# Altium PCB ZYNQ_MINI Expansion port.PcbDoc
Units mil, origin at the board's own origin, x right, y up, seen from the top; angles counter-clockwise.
Board outline 3075.9 x 3587.68 mil, 12 copper layers (Top Layer 1, Mid-Layer 2, Mid-Layer 3, Mid-Layer 4, Mid-Layer 5, Mid-Layer 6, Mid-Layer 7, Mid-Layer 8, Mid-Layer 9, Mid-Layer 10, Mid-Layer 11, Bottom Layer 12), stack 61.812 mil thick; 3 components, 0 nets, 80 pads, 24 vias.
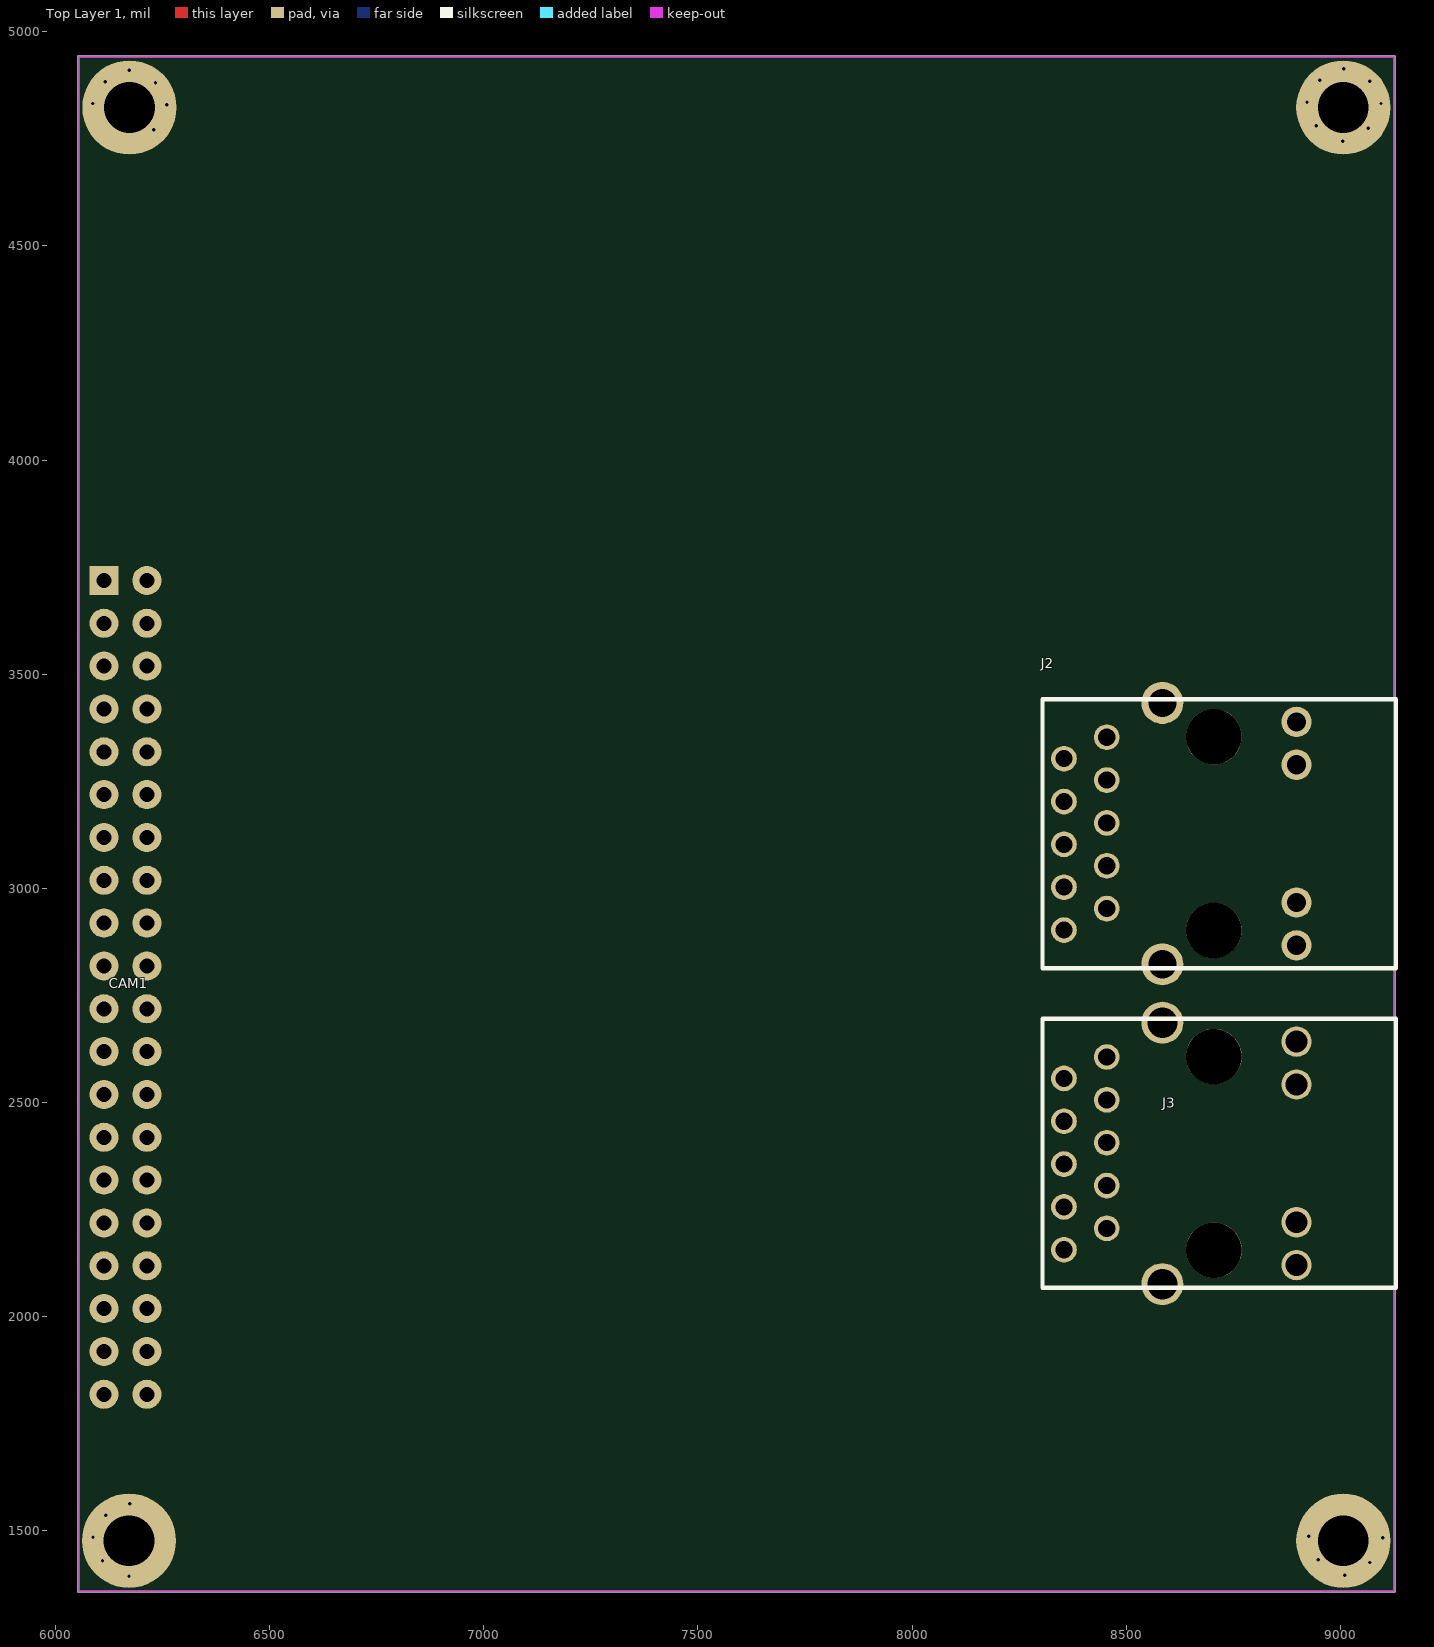
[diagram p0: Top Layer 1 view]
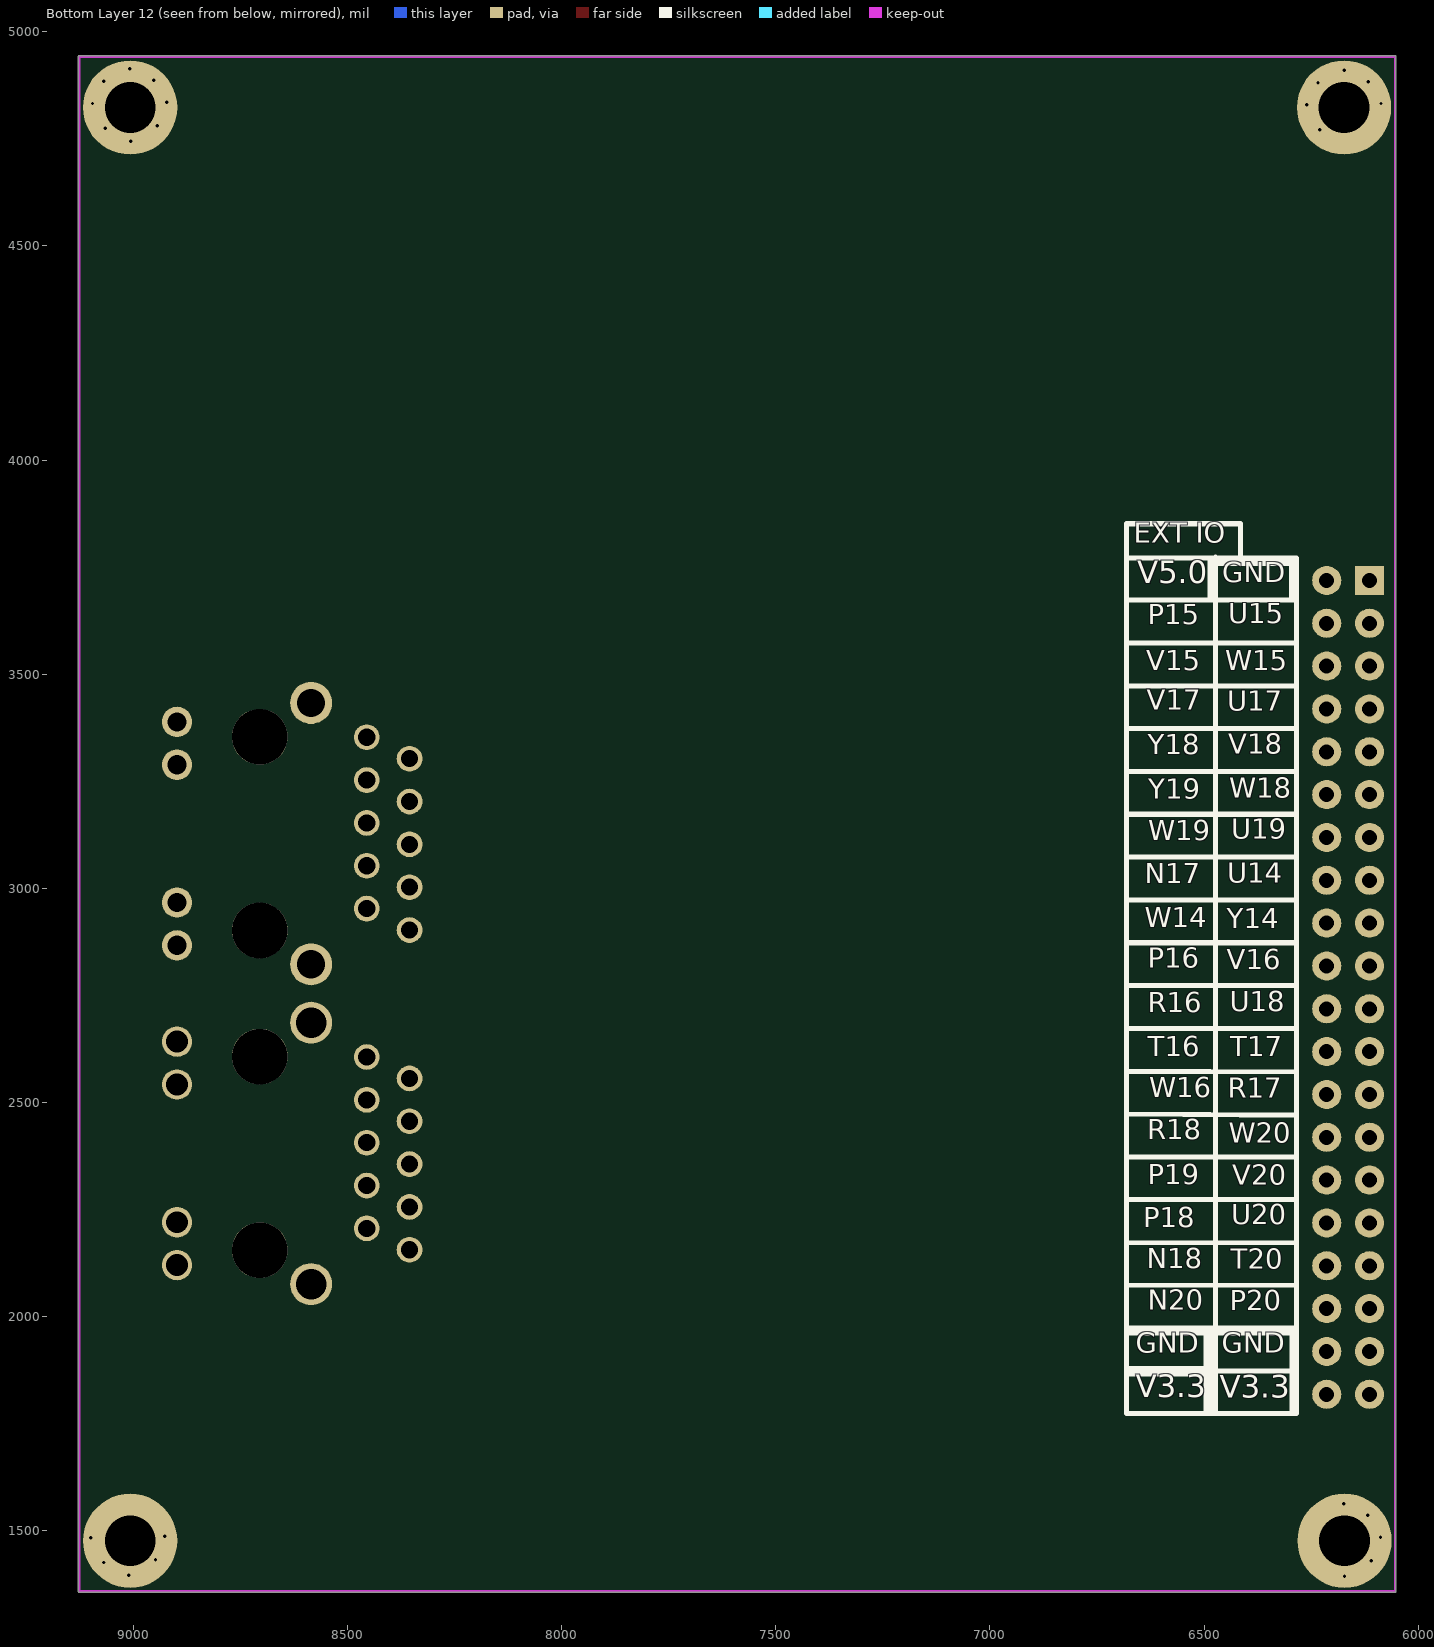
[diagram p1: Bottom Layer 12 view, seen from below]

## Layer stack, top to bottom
Top Solder: solder mask 0.4, Solder Resist, Dk 3.5
Top Layer 1: signal copper 1.378
Dielectric 1: core 2.9528, FR-4, Dk 4.2
Mid-Layer 2: signal copper 0.689
Dielectric 2: prepreg 4.5276, FR-4, Dk 4.2
Mid-Layer 3: signal copper 0.689
Dielectric 3: core 5.9055, FR-4, Dk 4.2
Mid-Layer 4: signal copper 0.689
Dielectric 4: prepreg 4.5276, FR-4, Dk 4.2
Mid-Layer 5: signal copper 0.689
Dielectric 5: core 5.9055, Dk 4.2
Mid-Layer 6: signal copper 0.689
Dielectric 6: prepreg 4.5276, Dk 4.2
Mid-Layer 7: signal copper 0.689
Dielectric 7: core 5.9055, Dk 4.2
Mid-Layer 8: signal copper 0.689
Dielectric 8: prepreg 4.5276, Dk 4.2
Mid-Layer 9: signal copper 0.689
Dielectric 9: core 5.9055, Dk 4.2
Mid-Layer 10: signal copper 0.689
Dielectric 10: prepreg 4.5276, Dk 4.2
Mid-Layer 11: signal copper 0.689
Dielectric 11: core 2.9528, FR-4, Dk 4.2
Bottom Layer 12: signal copper 1.378
Bottom Solder: solder mask 0.4, Solder Resist, Dk 3.5

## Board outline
6052.06,2142.67 cw(c6054.57,2142.69) 6052.06,2142.69 6052.06,4941.65 cw(c6054.57,4941.65) 6054.57,4944.17 7925.88,4944.17 cw(c7925.88,4941.65) 7925.91,4944.17 9125.44,4944.17 cw(c9125.44,4941.65) 9127.96,4941.65 9127.96,1359 cw(c9125.44,1359) 9125.44,1356.48 6054.57,1356.48 cw(c6054.57,1359) 6052.06,1359

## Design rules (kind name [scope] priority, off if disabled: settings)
AssemblyTestPointUsage [All] p1 off:
AssemblyTestpoint [All] p1 off: testpointundercomponent=TRUE minsize=40 maxsize=100 preferedsize=60 minholesize=0 maxholesize=40 preferedholesize=32 testpointgrid=1 usegrid=TRUE gridtolerance=0.01 allowsidetop=TRUE allowsidebottom=TRUE
Clearance Clearance_2 [IsTrack vs isvia] p1: gap=5.5 ignorepadtopadclearanceinfootprint=FALSE
Clearance [All] p2: gap=4 ignorepadtopadclearanceinfootprint=FALSE
ComponentClearance [All] p1 off: gap=10 collisioncheckmode=3 verticalgap=10 showdistances=FALSE
DiffPairsRouting [All] p1 off: maxlimit=10 minlimit=10 mostfreqgap=10 toplayer_minwidth=15 toplayer_maxwidth=15 toplayer_prefwidth=15 midlayer1_minwidth=15 midlayer1_maxwidth=15 midlayer1_prefwidth=15 midlayer2_minwidth=15 midlayer2_maxwidth=15 midlayer2_prefwidth=15 midlayer3_minwidth=15 midlayer3_maxwidth=15 midlayer3_prefwidth=15 midlayer4_minwidth=15 midlayer4_maxwidth=15 midlayer4_prefwidth=15 midlayer5_minwidth=15 midlayer5_maxwidth=15 midlayer5_prefwidth=15 midlayer6_minwidth=15 midlayer6_maxwidth=15 midlayer6_prefwidth=15 midlayer7_minwidth=15 midlayer7_maxwidth=15 midlayer7_prefwidth=15 midlayer8_minwidth=15 midlayer8_maxwidth=15 midlayer8_prefwidth=15 midlayer9_minwidth=15 midlayer9_maxwidth=15 midlayer9_prefwidth=15 midlayer10_minwidth=15 midlayer10_maxwidth=15 midlayer10_prefwidth=15 bottomlayer_minwidth=15 bottomlayer_maxwidth=15 bottomlayer_prefwidth=15 maxuncoupledlength=500
FabricationTestPointUsage [All] p1 off: valid=0 allowmultiple=FALSE
FabricationTestpoint [All] p1 off: side=3 testpointundercomponent=TRUE minsize=40 maxsize=100 preferedsize=60 minholesize=0 maxholesize=40 preferedholesize=32 testpointgrid=1 allowsidetop=TRUE allowsidebottom=TRUE usegrid=TRUE gridtolerance=0.01
FanoutControl Fanout_BGA [IsBGA] p1 off: bgadir=Out bgaviamode=Centered fanoutstyle=Auto fanoutdirection=Alternating viagrid=1 // Fanout_BGA (Default Rule)
FanoutControl Fanout_LCC [IsLCC] p2 off: bgadir=Out bgaviamode=Centered fanoutstyle=Auto fanoutdirection=Alternating viagrid=1 // Fanout_LCC (Default Rule)
FanoutControl Fanout_SOIC [IsSOIC] p3 off: bgadir=Out bgaviamode=Centered fanoutstyle=Auto fanoutdirection=Alternating viagrid=1 // Fanout_SOIC (Default Rule)
FanoutControl Fanout_Small [(CompPinCount < 5)] p4 off: bgadir=Out bgaviamode=Centered fanoutstyle=Auto fanoutdirection=OutThenIn viagrid=1 // Fanout_Small (Default Rule)
FanoutControl Fanout_Default [All] p5 off: bgadir=Out bgaviamode=Centered fanoutstyle=Auto fanoutdirection=Alternating viagrid=1 // Fanout_Default (Default Rule)
Height [All] p1 off: minheight=0 maxheight=1000 prefheight=500
HoleSize [All] p1 off: absolutevalues=TRUE maxlimit=100 minlimit=1 maxpercent=80.000 minpercent=20.000
HoleToHoleClearance [All] p1 off: gap=10 allowstackedmicrovias=TRUE
LayerPairs [All] p1 off: enforce=TRUE
MinimumSolderMaskSliver [All] p1 off: minsoldermaskwidth=10
NetAntennae [All] p1 off: netantennaetolerance=0
PasteMaskExpansion [All] p1 off: expansion=0
PlaneConnect [All] p1: planeconnectstyle=Direct reliefexpansion=20 reliefentries=4 reliefconductorwidth=10 reliefairgap=10
PolygonConnect [All] p1: connectstyle=Direct reliefconductorwidth=10 reliefentries=4 polygonreliefangle="90 Angle" airgapwidth=10
RoutingCorners [All] p1 off: cornerstyle=45-Degree minsetback=100 maxsetback=100
RoutingLayers [All] p1 off: top layer_v5=TRUE mid layer 1_v5=TRUE mid layer 2_v5=TRUE mid layer 3_v5=TRUE mid layer 4_v5=TRUE mid layer 5_v5=TRUE mid layer 6_v5=TRUE mid layer 7_v5=TRUE mid layer 8_v5=TRUE mid layer 9_v5=TRUE mid layer 10_v5=TRUE bottom layer_v5=TRUE
RoutingPriority [All] p1 off: routingpriority=0
RoutingTopology [All] p1 off: topology=Shortest
RoutingVias [All] p1: holewidth=7.87 width=15.75 viastyle="Through Hole" minholewidth=7.87 minwidth=15.75 maxholewidth=129.92 maxwidth=196.85
SilkToSilkClearance [All] p1 off: silktosilkclearance=10
SilkToSolderMaskClearance [IsPad] p1 off: minsilkscreentomaskgap=10 clearancetoexposedcopper=TRUE
SolderMaskExpansion [All] p1 off: expansion=4
UnpouredPolygon [All] p1 off:
Width [All] p1: maxlimit=20 minlimit=3.5 preferedwidth=3.9 toplayer_prefwidth=4.5 midlayer1_maxwidth=8 midlayer2_maxwidth=8 midlayer3_maxwidth=8 midlayer4_maxwidth=8 midlayer5_maxwidth=8 midlayer6_maxwidth=8 midlayer7_maxwidth=8 midlayer8_maxwidth=8 midlayer9_maxwidth=8 midlayer10_maxwidth=8 bottomlayer_prefwidth=4.5 minimp=50.000000 maximp=50.000000 favimp=50.000000
4 further rules are at their usual default settings.

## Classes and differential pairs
component class 09ZYNQ_IO: CAM1
component class 07ZYNQ_ETH_PHY: C144
component class 12_OLED: C? J?

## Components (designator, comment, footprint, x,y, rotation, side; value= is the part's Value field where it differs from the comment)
CAM1 "40针双排" 40针双排 6117.63,2721.92 r0 top locked
J2 "HR911130A" HR911130A#1 8701.62,3129.53 r0 top locked
J3 "HR911130A" HR911130A#2 8701.63,2383.07 r0 top locked

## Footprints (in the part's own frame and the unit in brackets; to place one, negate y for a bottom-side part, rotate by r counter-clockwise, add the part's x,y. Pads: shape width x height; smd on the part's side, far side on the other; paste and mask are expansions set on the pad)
40针双排 [mil]
  rect 68x68 hole 35: 1(-4,997)
  round 68 hole 35: 2(-4,897) 3(-4,797) 4(-4,697) 5(-4,597) 6(-4,497) 7(-4,397) 8(-4,297) 9(-4,197) 10(-4,97) 11(-4,-3) 12(-4,-103) 13(-4,-203) 14(-4,-303) 15(-4,-403) 16(-4,-503) 17(-4,-603) 18(-4,-703) 19(-4,-803) 20(-4,-903) 21(96,-903) 22(96,-803) 23(96,-703) 24(96,-603) 25(96,-503) 26(96,-403) 27(96,-303) 28(96,-203) 29(96,-103) 30(96,-3) 31(96,97) 32(96,197) 33(96,297) 34(96,397) 35(96,497) 36(96,597) 37(96,697) 38(96,797) 39(96,897) 40(96,997)
HR911130A#1 [mil]
  round 70.87 hole 45: 11(196,-262.54) 12(196,-162.54) 13(196,159.12) 14(196,259.12)
  round 98 hole 66: 15(-116.99,-306.83) 16(-116.99,303.41)
  round 129.92 hole 129.92: 17(3.08,-227.69) 18(3.08,224.27)
  round 60 hole 40: P1(-346.92,-226.71) P2(-246.92,-176.71) P3(-346.92,-126.71) P4(-246.92,-76.71) P5(-346.92,-26.71) P6(-246.92,23.29) P7(-346.92,73.29) P8(-246.92,123.29) P9(-346.92,173.29) P10(-246.92,223.29)
  silkscreen extent -397,-316 428,312
HR911130A#2 [mil]
  round 70.87 hole 51.18: 11(196,-262.54) 12(196,-162.54) 13(196,159.12) 14(196,259.12)
  round 98 hole 70.87: 15(-116.99,-306.83) 16(-116.99,303.41)
  round 129.92 hole 129.92: 17(3.08,-227.69) 18(3.08,224.27)
  round 60 hole 40: P1(-346.92,-226.71) P2(-246.92,-176.71) P3(-346.92,-126.71) P4(-246.92,-76.71) P5(-346.92,-26.71) P6(-246.92,23.29) P7(-346.92,73.29) P8(-246.92,123.29) P9(-346.92,173.29) P10(-246.92,223.29)
  silkscreen extent -397,-316 428,312

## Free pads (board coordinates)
  round 220 hole 118.5: 2(6172,1477) 2(6173,4823) 2(9007,1477) 2(9007,4823)

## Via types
v1: diameter 15.75, hole 7.87, Top Layer 1 to Bottom Layer 12, tented both sides, 24 vias

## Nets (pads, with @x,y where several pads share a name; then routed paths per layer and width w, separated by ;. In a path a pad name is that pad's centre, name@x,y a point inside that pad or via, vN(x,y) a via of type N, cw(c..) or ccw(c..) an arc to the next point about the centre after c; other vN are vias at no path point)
pads on no net: CAM1.1 CAM1.2 CAM1.3 CAM1.4 CAM1.5 CAM1.6 CAM1.7 CAM1.8 CAM1.9 CAM1.10 CAM1.11 CAM1.12 CAM1.13 CAM1.14 CAM1.15 CAM1.16 CAM1.17 CAM1.18 CAM1.19 CAM1.20 CAM1.21 CAM1.22 CAM1.23 CAM1.24 CAM1.25 CAM1.26 CAM1.27 CAM1.28 CAM1.29 CAM1.30 CAM1.31 CAM1.32 CAM1.33 CAM1.34 CAM1.35 CAM1.36 CAM1.37 CAM1.38 CAM1.39 CAM1.40 J2.11 J2.12 J2.13 J2.14 J2.15 J2.16 J2.17 J2.18 J2.P1 J2.P2 J2.P3 J2.P4 J2.P5 J2.P6 J2.P7 J2.P8 J2.P9 J2.P10 J3.11 J3.12 J3.13 J3.14 J3.15 J3.16 J3.17 J3.18 J3.P1 J3.P2 J3.P3 J3.P4 J3.P5 J3.P6 J3.P7 J3.P8 J3.P9 J3.P10
copper on no net:
  other v1: 6172,1394.25 9010,1396.25 9069,1426.25 6110,1430.25 8948,1432.25 9099,1484.25 6088,1485.25 8926,1487.25 6118,1536.25 6174,1563.25 9006,4744.25 6230,4771.25 9065,4774.25 8944,4780.25 6260,4829.25 6087,4832.25 9095,4832.25 8922,4835.25 6234,4881.25 6117,4883.25 9069,4884.25 8952,4886.25 6173,4910.25 9008,4913.25

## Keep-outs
Keep-Out Layer:
  lines w5: 6054.57,2142.69 6054.57,4941.65 7925.88,4941.65 ; 6054.57,2142.79 6054.57,1359 9125.44,1359 9125.44,4941.65 7801.69,4941.65 ; 7703.73,4941.39 8162.1,4941.39

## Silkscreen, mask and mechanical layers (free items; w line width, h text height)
Bottom Overlay:
  rectangle: 6473.08,3673.17 6491.68,3773.24
  rectangle: 6285.68,3752.73 6489.88,3773.24
  rectangle: 6284.38,3674.53 6301.98,3773.24
  rectangle: 6498.48,1859.93 6683.48,1885.23
  rectangle: 6472.78,1777.03 6500.98,1968.53
  rectangle: 6285.78,1776.63 6300.88,1972.23
  rectangle: 6285.78,1955.83 6678.98,1972.23
  lines w5: 6680.81,3773.24 6680.88,3773.24
  lines w12: 6284.38,3573.24 6284.38,1774.24 6680.88,1774.24 6680.88,3573.24 6680.88,3673.17 6680.81,3673.24 6285.68,3673.24 ; 6284.88,2973.24 6680.81,2973.24 ; 6285.28,3273.24 6680.81,3273.24 ; 6285.68,2673.24 6680.81,2673.24 ; 6285.68,3573.24 6680.81,3573.24 ; 6285.88,2773.24 6680.81,2773.24 ; 6285.88,2873.24 6680.81,2873.24 ; 6286.41,3472.24 6680.18,3472.24 ; 6286.88,1873.24 6680.81,1873.24 ; 6286.88,1973.34 6680.81,1973.24 ; 6286.88,2074.44 6680.81,2073.24 ; 6286.88,2273.64 6680.81,2273.24 ; 6286.88,2372.24 6680.81,2373.24 ; 6286.88,2470.24 6680.81,2473.24 ; 6286.88,2571.24 6680.81,2573.24 ; 6286.88,3173.24 6680.81,3173.24 ; 6287.18,3073.24 6680.81,3073.24 ; 6288.88,3373.24 6680.81,3373.24 ; 6433.88,3771.43 6414.88,3771.43 6414.88,3851.43 6680.88,3851.43 6680.88,3759.43 ; 6473.08,1775.94 6473.08,3572.24 6473.08,3673.24 ; 6473.08,3672.24 6473.08,3773.24 ; 6680.81,3773.24 6679,3771.43 6284.38,3771.43 6284.38,3673.24 ; 6680.88,3633.98 6680.88,3773.24 ; 6284.38,3673.24 6284.38,3511.43 6284.38,3673.24 ; 6286.88,2172.51 6680.81,2173.24 6286.88,2172.51
  text "EXT IO" at 6663.88,3790.43 h80
  text "GND" at 6457.18,3698.24 h80
  text "V5.0" at 6655.88,3695.43 h90
  text "U15" at 6444.03,3602.43 h80
  text "P15" at 6630.88,3600.43 h80
  text "W15" at 6451.03,3493.24 h80
  text "V15" at 6634.88,3493.24 h80
  text "V17" at 6633.88,3400.43 h80
  text "U17" at 6446.03,3398.24 h80
  text "V18" at 6444.03,3298.24 h80
  text "Y18" at 6631.03,3296.43 h80
  text "W18" at 6441.03,3195.24 h80
  text "Y19" at 6629.88,3192.43 h80
  text "U19" at 6436.03,3099.24 h80
  text "W19" at 6630.03,3096.43 h80
  text "U14" at 6445.88,2996.43 h80
  text "N17" at 6637.88,2995.43 h80
  text "W14" at 6638.03,2893.24 h80
  text "Y14" at 6447.03,2890.24 h80
  text "P16" at 6631.03,2798.24 h80
  text "V16" at 6447.03,2795.24 h80
  text "U18" at 6440.03,2697.24 h80
  text "R16" at 6631.88,2694.43 h80
  text "T17" at 6439.03,2591.24 h80
  text "T16" at 6631.03,2591.43 h80
  text "W16" at 6628.03,2496.24 h80
  text "R17" at 6445.11,2495.24 h80
  text "R18" at 6632.03,2397.74 h80
  text "W20" at 6442.03,2390.24 h80
  text "P19" at 6631.03,2293.24 h80
  text "V20" at 6434.03,2291.24 h80
  text "U20" at 6436.03,2199.24 h80
  text "P18" at 6642.03,2192.24 h80
  text "T20" at 6438.03,2096.24 h80
  text "N18" at 6634.03,2096.45 h80
  text "N20" at 6630.88,1999.43 h80
  text "P20" at 6440.03,1998.24 h80
  text "GND" at 6659.78,1899.84 h80
  text "GND" at 6458.18,1899.24 h80
  text "V3.3" at 6659.28,1794.64 h90
  text "V3.3" at 6463.58,1792.94 h90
